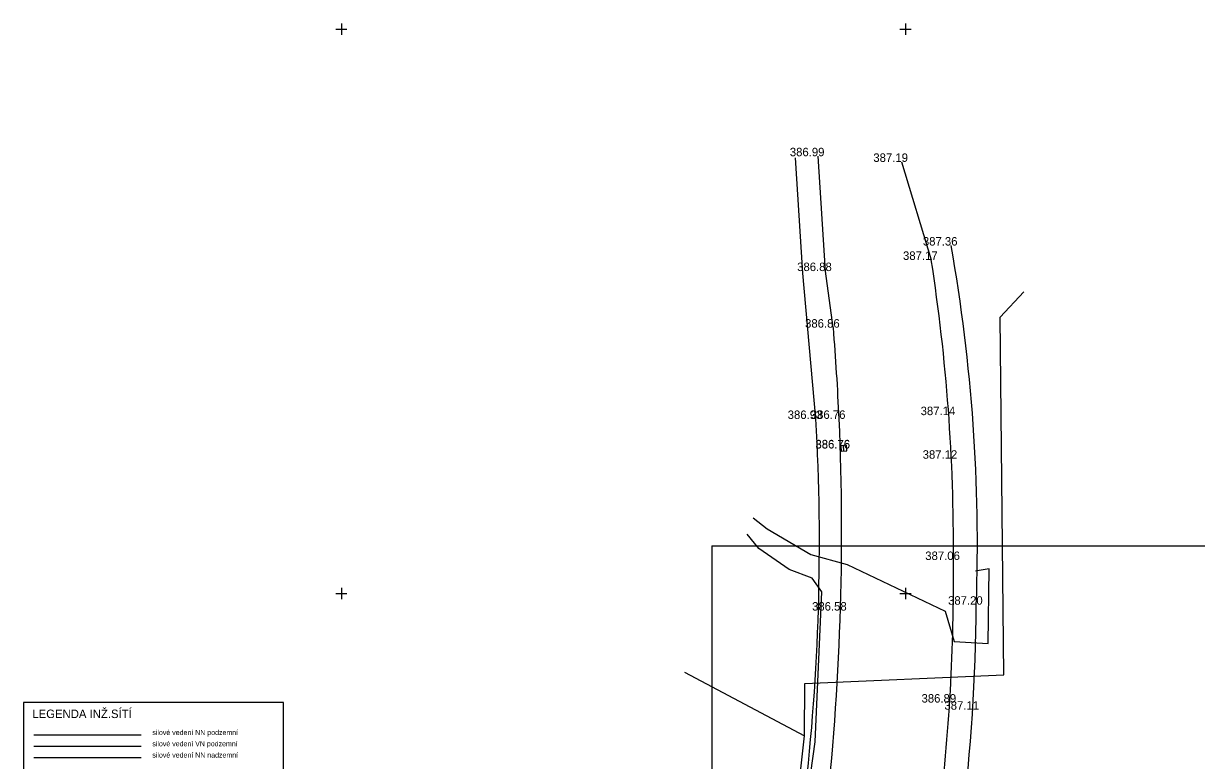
# Model space of a CAD drawing. Extents: x -438233 to -437334, y -1133133 to -1132623.
# Drawn here: x -438228.2 to -438124.2, y -1132914.8 to -1132849.5 of the extents above; entities that cross this region are included whole.
import ezdxf

# ---------------------------------------------------------------- set-up
doc = ezdxf.new("R2010")
doc.units = 0
for name, color, linetype in [('Vrstva 1', 7, 'Continuous'), ('Vrstva 10', 7, 'Continuous'), ('Vrstva 11', 7, 'Continuous'), ('Vrstva 27', 7, 'Continuous'), ('Vrstva 3', 7, 'Continuous'), ('Vrstva 42', 7, 'Continuous'), ('Vrstva 52', 7, 'Continuous'), ('Vrstva 53', 7, 'Continuous'), ('Vrstva 58', 7, 'Continuous'), ('Vrstva 61', 7, 'Continuous')]:
    doc.layers.add(name, color=color, linetype=linetype)

msp = doc.modelspace()

# ---------------------------------------------------------------- linework, layer by layer
at = {"layer": 'Vrstva 1'}
for p, q in [((-438157.76, -1132861.26), (-438157.76, -1132861.26)), ((-438150.36, -1132861.76), (-438150.36, -1132861.76)), ((-438145.97, -1132869.17), (-438145.97, -1132869.17)), ((-438147.73, -1132870.44), (-438147.73, -1132870.44)), ((-438157.11, -1132871.43), (-438157.11, -1132871.43)), ((-438156.41, -1132876.44), (-438156.41, -1132876.44)), ((-438157.95, -1132884.53), (-438157.95, -1132884.53)), ((-438155.9, -1132884.52), (-438155.9, -1132884.52)), ((-438146.17, -1132884.19), (-438146.17, -1132884.19)), ((-438155.49, -1132887.13), (-438155.49, -1132887.13)), ((-438155.49, -1132887.15), (-438155.49, -1132887.15)), ((-438145.99, -1132888.05), (-438145.99, -1132888.05)), ((-438167.16, -1132895.77), (-438167.16, -1133045.77)), ((-438167.16, -1132895.77), (-437957.16, -1132895.77)), ((-438145.76, -1132897.02), (-438145.76, -1132897.02)), ((-438143.74, -1132900.98), (-438143.74, -1132900.98)), ((-438155.79, -1132901.5), (-438155.79, -1132901.5)), ((-438146.09, -1132909.65), (-438146.09, -1132909.65)), ((-438144.06, -1132910.28), (-438144.06, -1132910.28))]:
    msp.add_line(p, q, dxfattribs=at)
at = {"layer": 'Vrstva 10'}
for points in [[(-438156.41, -1132876.44), (-438157.11, -1132871.43), (-438157.76, -1132861.26)], [(-438150.36, -1132861.76), (-438147.73, -1132870.44)]]:
    msp.add_lwpolyline(points, dxfattribs=at)
for centre, radius, start, end in [((-438312.18, -1132895.96), 166.42, 359.6351, 8.8186), ((-438377.17, -1132894.46), 221.5, 2.5715, 4.6659), ((-438384.63, -1132894.51), 228.96, 353.5753, 2.4999), ((-438319.39, -1132898.79), 173.63, 352.9385, 0.5852)]:
    msp.add_arc(centre, radius, start, end, dxfattribs=at)
at = {"layer": 'Vrstva 11'}
msp.add_lwpolyline([(-438157.95, -1132884.53), (-438159.1, -1132871.63), (-438159.76, -1132861.39)], dxfattribs=at)
for centre, radius, start, end in [((-438295.26, -1132895.64), 151.62, 357.9809, 10.0536), ((-438353.31, -1132895.52), 195.67, 353.359, 3.2199), ((-438315.62, -1132899.59), 171.89, 353.0761, 359.5381)]:
    msp.add_arc(centre, radius, start, end, dxfattribs=at)
at = {"layer": 'Vrstva 27'}
msp.add_line((-438155.47, -1132887.38), (-438155.5, -1132886.88), dxfattribs=at)
msp.add_lwpolyline([(-438155.22, -1132887.36), (-438155.25, -1132886.86), (-438155.75, -1132886.9), (-438155.72, -1132887.39)], close=True, dxfattribs=at)
at = {"layer": 'Vrstva 42'}
msp.add_lwpolyline([(-438228.17, -1132922.08), (-438205.12, -1132922.08), (-438205.12, -1132909.65), (-438228.17, -1132909.65)], close=True, dxfattribs=at)
at = {"layer": 'Vrstva 52'}
for p, q in [((-438227.25, -1132912.52), (-438217.75, -1132912.52)), ((-438227.25, -1132913.52), (-438217.75, -1132913.52))]:
    msp.add_line(p, q, dxfattribs=at)
for points in [[(-438163.5, -1132893.29), (-438162.27, -1132894.26), (-438158.4, -1132896.54), (-438155.17, -1132897.41), (-438146.49, -1132901.55), (-438145.69, -1132904.25), (-438142.7, -1132904.42)], [(-438142.7, -1132904.42), (-438142.6, -1132897.79), (-438143.48, -1132897.96), (-438143.81, -1132898.02)]]:
    msp.add_lwpolyline(points, dxfattribs=at)
at = {"layer": 'Vrstva 53'}
for p, q in [((-438169.58, -1132906.95), (-438158.96, -1132912.58)), ((-438158.96, -1132912.58), (-438158.94, -1132907.96))]:
    msp.add_line(p, q, dxfattribs=at)
for points in [[(-438158.94, -1132907.96), (-438141.3, -1132907.2), (-438141.62, -1132875.51), (-438139.52, -1132873.27)], [(-438164.46, -1132942.23), (-438162.24, -1132934.78), (-438159.33, -1132922.62), (-438158.02, -1132913.14), (-438157.41, -1132899.84), (-438158.29, -1132898.64), (-438160.31, -1132897.85), (-438163, -1132896.01), (-438164.04, -1132894.73)], [(-438171.57, -1132956.51), (-438167.71, -1132946.4), (-438163.02, -1132934.11), (-438159.99, -1132921.89), (-438158.96, -1132912.58)]]:
    msp.add_lwpolyline(points, dxfattribs=at)
at = {"layer": 'Vrstva 58'}
msp.add_line((-438227.25, -1132914.52), (-438217.75, -1132914.52), dxfattribs=at)
at = {"layer": 'Vrstva 61'}
for p, q in [((-438200, -1132849.5), (-438200, -1132850.5)), ((-438150, -1132849.5), (-438150, -1132850.5)), ((-438200.5, -1132850), (-438199.5, -1132850)), ((-438150.5, -1132850), (-438149.5, -1132850)), ((-438200.5, -1132900), (-438199.5, -1132900)), ((-438200, -1132899.5), (-438200, -1132900.5)), ((-438150.5, -1132900), (-438149.5, -1132900)), ((-438150, -1132899.5), (-438150, -1132900.5))]:
    msp.add_line(p, q, dxfattribs=at)

# ---------------------------------------------------------------- texts
at = {"layer": 'Vrstva 3'}
for s, p in [('386.99 ', (-438160.26, -1132861.26)), ('387.19 ', (-438152.86, -1132861.76)), ('387.36 ', (-438148.47, -1132869.17)), ('387.17 ', (-438150.23, -1132870.44)), ('386.88 ', (-438159.61, -1132871.43)), ('386.86 ', (-438158.91, -1132876.44)), ('386.93 ', (-438160.45, -1132884.53)), ('386.76 ', (-438158.4, -1132884.52)), ('387.14 ', (-438148.67, -1132884.19)), ('386.76 ', (-438157.99, -1132887.13)), ('386.76 ', (-438157.99, -1132887.15)), ('387.12 ', (-438148.49, -1132888.05)), ('387.06 ', (-438148.26, -1132897.02)), ('387.20 ', (-438146.24, -1132900.98)), ('386.58 ', (-438158.29, -1132901.5)), ('386.89 ', (-438148.59, -1132909.65)), ('387.11 ', (-438146.56, -1132910.28))]:
    msp.add_text(s, height=0.75, dxfattribs=at).set_placement(p)
at = {"layer": 'Vrstva 42'}
for s, height, p in [('LEGENDA INŽ.SÍTÍ', 0.75, (-438227.38, -1132911.02)), ('silové vedení NN podzemní', 0.45, (-438216.75, -1132912.52)), ('silové vedení VN podzemní', 0.45, (-438216.75, -1132913.52)), ('silové vedení NN nadzemní', 0.45, (-438216.75, -1132914.52))]:
    msp.add_text(s, height=height, dxfattribs=at).set_placement(p)

doc.saveas('drawing.dxf')
